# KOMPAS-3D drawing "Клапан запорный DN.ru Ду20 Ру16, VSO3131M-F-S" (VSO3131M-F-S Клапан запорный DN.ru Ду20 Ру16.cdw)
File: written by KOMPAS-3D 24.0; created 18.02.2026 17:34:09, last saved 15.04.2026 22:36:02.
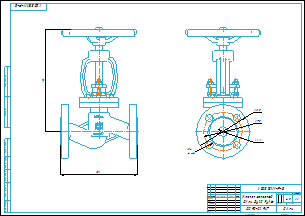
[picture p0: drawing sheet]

Document properties: Автор: R2D2; Форматы листов документа: A2; Полное имя файла: VSO3131M-F-S Клапан запорный DN.ru Ду20 Ру16.m3d; Масса: 4.05; Наименование: Клапан запорный DN.ru Ду20 Ру16; Количество листов документа: 1; Примечание: D090-02947

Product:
- Part/product: Клапан запорный DN.ru Ду20 Ру16  | designation VSO3131M-F-S
    Масса: 4.05
    Раздел спецификации: Прочие изделия
    Примечание: D090-02947

Views: Вид 1, Спереди, Проекционный вид 2
Referenced files in E:\Работа\Зайцев\VSO3131M-F-S Клапан запорный DN.ru Ду15-100 Ру40\DN20\: VSO3131M-F-S Клапан запорный DN.ru Ду20 Ру40.m3d
Referenced files in E:\Работа\Зайцев\VSO3131M-F-S Клапан запорный DN.ru Ду15-100 Ру16\DN20\: VSO3131M-F-S Клапан запорный DN.ru Ду20 Ру16.m3d
Referenced files in E:\Работа\Зайцев\Для компаса\: чертеж DN.ru А3.cdt
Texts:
  VSO3131M-F-S
  чертеж DN.ru А3.cdt
  Клапан запорный
  DN.ru Ду20 Ру16
  Клапан запорный DN.ru Ду20 Ру16
  VSO3131M-F-S Клапан запорный DN.ru Ду20 Ру16
Dimensions and other numbers on the sheet: 0; 3; 2; 4; 150; 200; 105; 75; 20; 14; 4 отв.; 1:1; 1; 4,05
